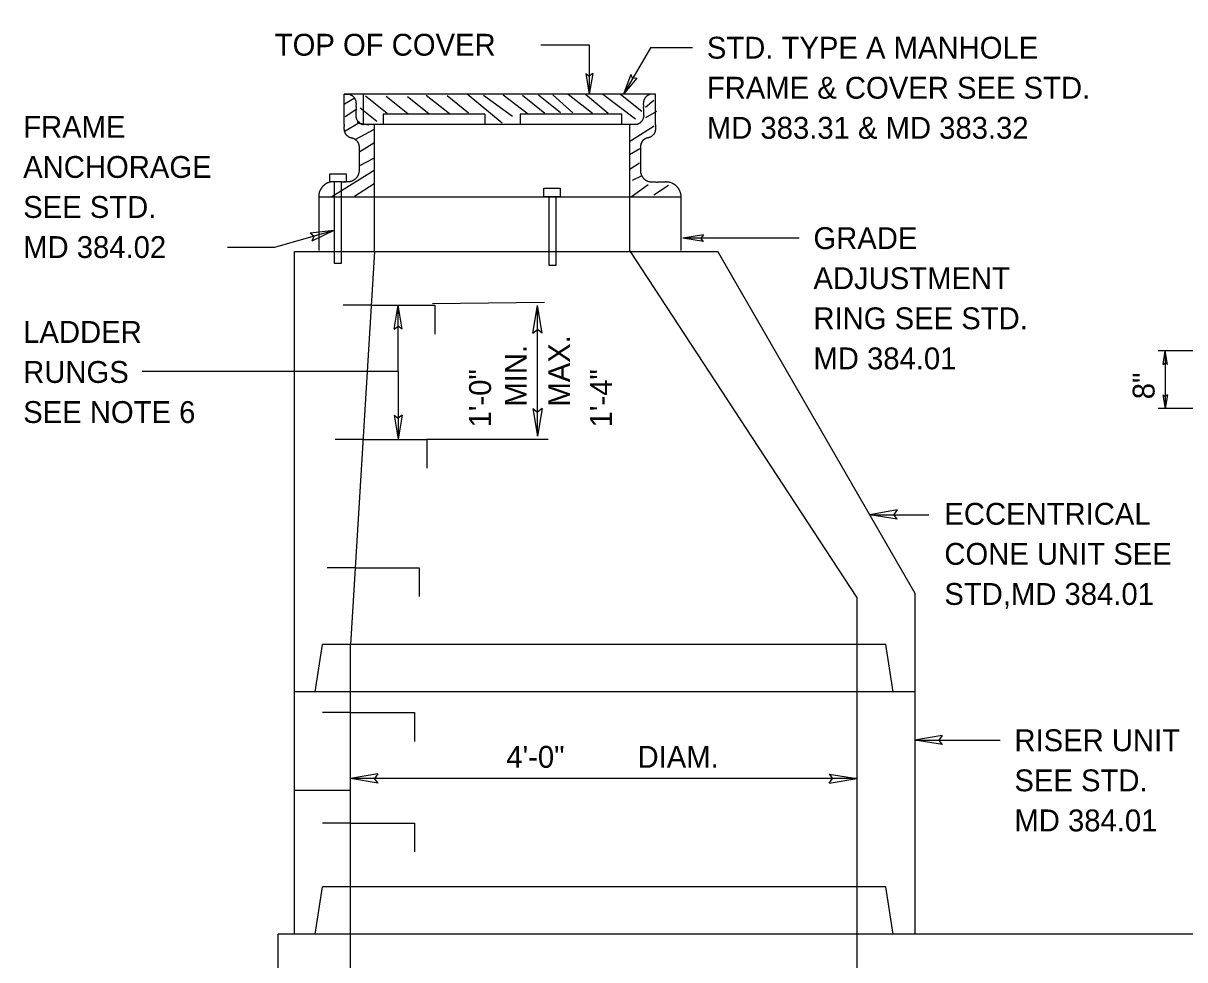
# Model space of a CAD drawing. Extents: x 1.8 to 9.1, y -6 to 4.
# Drawn here: x 1.845 to 5.032, y -0.238 to 2.333 of the extents above; entities that cross this region are included whole.
import ezdxf

# ---------------------------------------------------------------- set-up
doc = ezdxf.new("R2010")
doc.units = 0
for name, color, linetype in [('DETL-DIMS', 7, 'Continuous'), ('DETL-LINE', 7, 'Continuous'), ('DETL-NOTE', 7, 'Continuous'), ('DETL-PATT', 7, 'Continuous')]:
    doc.layers.add(name, color=color, linetype=linetype)

msp = doc.modelspace()

# ---------------------------------------------------------------- linework, layer by layer
at = {"layer": 'DETL-DIMS'}
for p, q in [((3.2647, 2.2738), (3.3979, 2.2738)), ((3.3979, 2.2738), (3.3979, 2.1382)), ((3.5656, 2.2657), (3.492, 2.1382)), ((3.6811, 2.2657), (3.5656, 2.2657)), ((3.3885, 2.1948), (3.3979, 2.1382)), ((3.3885, 2.1948), (3.3979, 2.1877)), ((3.4073, 2.1948), (3.3979, 2.1382)), ((3.4073, 2.1948), (3.3979, 2.1877)), ((3.5122, 2.1919), (3.492, 2.1382)), ((3.5285, 2.1825), (3.492, 2.1382)), ((3.5122, 2.1919), (3.5168, 2.1811)), ((3.5285, 2.1825), (3.5168, 2.1811)), ((2.5351, 1.7185), (2.6983, 1.7645)), ((2.6317, 1.7572), (2.6983, 1.7645)), ((2.6317, 1.7572), (2.6427, 1.7488)), ((2.6377, 1.736), (2.6983, 1.7645)), ((2.6377, 1.736), (2.6427, 1.7488)), ((3.711, 1.7524), (3.6544, 1.743)), ((3.9735, 1.743), (3.6544, 1.743)), ((3.711, 1.7335), (3.6544, 1.743)), ((3.711, 1.7524), (3.704, 1.743)), ((3.711, 1.7335), (3.704, 1.743)), ((2.4048, 1.7185), (2.5351, 1.7185)), ((2.9675, 1.5639), (3.2747, 1.567)), ((2.8623, 1.4931), (2.8733, 1.5592)), ((2.8733, 1.3766), (2.8733, 1.5592)), ((2.8843, 1.4931), (2.8733, 1.5592)), ((3.2431, 1.4826), (3.2557, 1.5581)), ((3.2557, 1.1996), (3.2557, 1.5581)), ((3.2683, 1.4826), (3.2557, 1.5581)), ((2.8623, 1.4931), (2.8733, 1.5014)), ((2.8843, 1.4931), (2.8733, 1.5014)), ((3.2431, 1.4826), (3.2557, 1.4921)), ((3.2683, 1.4826), (3.2557, 1.4921)), ((5.0766, 1.4338), (4.9586, 1.4338)), ((4.9721, 1.3961), (4.9783, 1.4338)), ((4.9847, 1.3961), (4.9783, 1.4338)), ((4.9783, 1.4338), (4.9783, 1.275)), ((2.8733, 1.3766), (2.1711, 1.3766)), ((2.8733, 1.3766), (2.8733, 1.1913)), ((4.9721, 1.3961), (4.9784, 1.4008)), ((4.9847, 1.3961), (4.9784, 1.4008)), ((4.9719, 1.3128), (4.9783, 1.275)), ((4.9719, 1.3128), (4.9782, 1.3081)), ((4.9845, 1.3128), (4.9782, 1.3081)), ((4.9845, 1.3128), (4.9783, 1.275)), ((3.2431, 1.275), (3.2557, 1.1996)), ((3.2431, 1.275), (3.2557, 1.2656)), ((3.2683, 1.275), (3.2557, 1.1996)), ((3.2683, 1.275), (3.2557, 1.2656)), ((5.1362, 1.275), (4.9586, 1.275)), ((2.8623, 1.2573), (2.8733, 1.1913)), ((2.8623, 1.2573), (2.8733, 1.2491)), ((2.8843, 1.2573), (2.8733, 1.1913)), ((2.8843, 1.2573), (2.8733, 1.2491)), ((3.2852, 1.1906), (2.9514, 1.1904)), ((4.2425, 0.9973), (4.1673, 0.9832)), ((4.2425, 0.9973), (4.2333, 0.9845)), ((4.243, 0.9721), (4.1673, 0.9832)), ((4.1673, 0.9832), (4.3297, 0.9832)), ((4.243, 0.9721), (4.2333, 0.9845)), ((4.3663, 0.3782), (4.2909, 0.3648)), ((4.3665, 0.353), (4.2909, 0.3648)), ((4.2909, 0.3648), (4.5249, 0.3648)), ((4.3663, 0.3782), (4.357, 0.3655)), ((4.3665, 0.353), (4.357, 0.3655)), ((2.8181, 0.2725), (2.7427, 0.2598)), ((2.8182, 0.2474), (2.7427, 0.2598)), ((4.1315, 0.2598), (2.7427, 0.2598)), ((2.8181, 0.2725), (2.8087, 0.2599)), ((2.8182, 0.2474), (2.8087, 0.2599)), ((4.0559, 0.2722), (4.1315, 0.2598)), ((4.0559, 0.2722), (4.0654, 0.2597)), ((4.056, 0.2471), (4.1315, 0.2598)), ((4.056, 0.2471), (4.0654, 0.2597))]:
    msp.add_line(p, q, dxfattribs=at)
at = {"layer": 'DETL-LINE'}
for p, q in [((3.5794, 2.1382), (2.7249, 2.1382)), ((2.7249, 2.0553), (2.7249, 2.1382)), ((2.778, 2.0545), (2.778, 2.1382)), ((3.5794, 2.0553), (3.5794, 2.1382)), ((2.8324, 2.0837), (2.8324, 2.0545)), ((3.1115, 2.0837), (2.8324, 2.0837)), ((3.1115, 2.0837), (3.1115, 2.0545)), ((3.208, 2.0837), (3.208, 2.0545)), ((3.4874, 2.0837), (3.208, 2.0837)), ((3.4874, 2.0545), (3.4874, 2.0837)), ((3.5262, 2.0545), (2.778, 2.0545)), ((2.8081, 1.7066), (2.8081, 2.0545)), ((3.5093, 1.7095), (3.5093, 2.0545)), ((2.7661, 1.9934), (2.7661, 1.9263)), ((3.5382, 1.9934), (3.5382, 1.9263)), ((2.686, 1.8978), (2.686, 1.9196)), ((2.686, 1.9196), (2.7308, 1.9196)), ((2.7308, 1.9196), (2.7308, 1.8978)), ((2.6983, 1.8978), (2.686, 1.8978)), ((2.7184, 1.8978), (2.7308, 1.8978)), ((2.6554, 1.8564), (3.6489, 1.8564)), ((2.6554, 1.8564), (2.6554, 1.7095)), ((3.2731, 1.8564), (3.2731, 1.88)), ((3.2731, 1.88), (3.318, 1.88)), ((3.318, 1.8564), (3.2731, 1.8564)), ((3.2869, 1.8564), (3.2869, 1.6688)), ((3.3071, 1.6688), (3.3071, 1.8564)), ((3.318, 1.88), (3.318, 1.8564)), ((3.6489, 1.8564), (3.6489, 1.7095)), ((2.5894, -0.167), (2.5894, 1.7066)), ((2.5894, 1.7066), (3.7498, 1.7066)), ((2.8081, 1.7066), (2.7427, 0.6274)), ((4.1315, 0.758), (3.5093, 1.7095)), ((3.7498, 1.7076), (4.2909, 0.7687)), ((3.2869, 1.6688), (3.3071, 1.6688)), ((2.7992, 1.5591), (2.7225, 1.5591)), ((2.7768, 1.1908), (2.7002, 1.1908)), ((2.7554, 0.8382), (2.6788, 0.8382)), ((4.2909, 0.7687), (4.2909, -0.167)), ((4.1315, 0.758), (4.1315, -0.412)), ((2.6461, 0.4982), (2.666, 0.6274)), ((4.2112, 0.6274), (2.666, 0.6274)), ((2.7427, -3.2344), (2.7427, 0.6274)), ((4.2312, 0.4982), (4.2112, 0.6274)), ((2.6461, 0.4982), (2.5894, 0.4982)), ((4.2312, 0.4982), (2.6461, 0.4982)), ((4.2909, 0.4982), (4.2312, 0.4982)), ((2.7427, 0.4409), (2.666, 0.4409)), ((2.5894, 0.2282), (2.7427, 0.2282)), ((2.7427, 0.1375), (2.666, 0.1375)), ((2.6461, -0.167), (2.666, -0.0377)), ((4.2112, -0.0377), (2.666, -0.0377)), ((4.2312, -0.167), (4.2112, -0.0377)), ((2.5439, -3.4727), (2.5439, -0.167)), ((2.6461, -0.167), (2.5439, -0.167)), ((4.2312, -0.167), (2.6461, -0.167)), ((5.0988, -0.167), (4.2312, -0.167))]:
    msp.add_line(p, q, dxfattribs=at)
msp.add_lwpolyline([(2.6983, 1.8978), (2.6983, 1.674), (2.7184, 1.674), (2.7184, 1.8978)], close=True, dxfattribs=at)
for points in [[(2.7992, 1.5591), (2.9744, 1.5591), (2.9744, 1.4799)], [(2.7768, 1.1908), (2.952, 1.1908), (2.952, 1.1115)], [(2.7554, 0.8382), (2.9307, 0.8382), (2.9307, 0.759)], [(2.7427, 0.4409), (2.9179, 0.4409), (2.9179, 0.3617)], [(2.7427, 0.1375), (2.9179, 0.1375), (2.9179, 0.0582)]]:
    msp.add_lwpolyline(points, dxfattribs=at)
msp.add_circle((5.69, 3.1109), 0.829, dxfattribs=at)
msp.add_arc((3.5635, 1.9935), 0.0253, 100.5321, 180.1949, dxfattribs=at)
for points in [[(2.7249, 2.1382), (2.7353, 2.138), (2.7405, 2.1373), (2.7437, 2.1361), (2.7452, 2.1353), (2.747, 2.1342), (2.7488, 2.1329), (2.75, 2.1317), (2.7508, 2.131), (2.7512, 2.1306), (2.7517, 2.13), (2.7524, 2.1292), (2.7529, 2.1285), (2.7536, 2.1277), (2.7543, 2.1266), (2.755, 2.1251), (2.7554, 2.1244), (2.7561, 2.1227), (2.7568, 2.1206), (2.7572, 2.1189), (2.7575, 2.1169), (2.7575, 2.115), (2.758, 2.1131), (2.7581, 2.1098), (2.7577, 2.1075), (2.7579, 2.1023), (2.7584, 2.1009), (2.758, 2.099), (2.7581, 2.0948), (2.7576, 2.0934), (2.7578, 2.0887), (2.7573, 2.0872), (2.7575, 2.0816), (2.7571, 2.0797), (2.7572, 2.0769), (2.7577, 2.075), (2.7579, 2.0737), (2.7588, 2.0705), (2.7602, 2.068), (2.761, 2.0664), (2.762, 2.0652), (2.7631, 2.0636), (2.7642, 2.0625), (2.765, 2.0617), (2.7657, 2.0611), (2.7663, 2.0604), (2.7672, 2.0596), (2.769, 2.0584), (2.7708, 2.0573), (2.7716, 2.0569), (2.7723, 2.0565), (2.7734, 2.056), (2.7752, 2.0553), (2.778, 2.0545)], [(3.5794, 2.1382), (3.5689, 2.138), (3.5638, 2.1373), (3.5606, 2.1361), (3.5591, 2.1353), (3.5573, 2.1342), (3.5555, 2.1329), (3.5543, 2.1317), (3.5534, 2.131), (3.553, 2.1306), (3.5526, 2.13), (3.5519, 2.1292), (3.5514, 2.1285), (3.5507, 2.1277), (3.55, 2.1266), (3.5493, 2.1251), (3.5488, 2.1244), (3.5482, 2.1227), (3.5475, 2.1206), (3.5471, 2.1189), (3.5468, 2.1169), (3.5467, 2.115), (3.5463, 2.1131), (3.5461, 2.1098), (3.5466, 2.1075), (3.5464, 2.1023), (3.5459, 2.1009), (3.5463, 2.099), (3.5462, 2.0948), (3.5466, 2.0934), (3.5465, 2.0887), (3.5469, 2.0872), (3.5467, 2.0816), (3.5472, 2.0797), (3.5471, 2.0769), (3.5466, 2.075), (3.5464, 2.0737), (3.5454, 2.0705), (3.544, 2.068), (3.5433, 2.0664), (3.5423, 2.0652), (3.5412, 2.0636), (3.5401, 2.0625), (3.5393, 2.0617), (3.5386, 2.0611), (3.5379, 2.0604), (3.5371, 2.0596), (3.5353, 2.0584), (3.5335, 2.0573), (3.5327, 2.0569), (3.532, 2.0565), (3.5309, 2.056), (3.5291, 2.0553), (3.5262, 2.0545)], [(2.7249, 2.0553), (2.7249, 2.0533), (2.7248, 2.0517), (2.7249, 2.0506), (2.7247, 2.0491), (2.7246, 2.0473), (2.7247, 2.046), (2.7247, 2.0433), (2.7248, 2.0423), (2.7249, 2.0407), (2.7251, 2.0392), (2.7254, 2.0373), (2.7258, 2.0357), (2.7262, 2.0346), (2.7265, 2.0339), (2.7269, 2.033), (2.7276, 2.0315), (2.7286, 2.0297), (2.7297, 2.0281), (2.7307, 2.0268), (2.7319, 2.0257), (2.7326, 2.0248), (2.7333, 2.0243), (2.7354, 2.0225), (2.7371, 2.0215), (2.7387, 2.0206), (2.7395, 2.0202), (2.741, 2.0196), (2.742, 2.0192), (2.7433, 2.0188), (2.7451, 2.0185), (2.747, 2.018), (2.7495, 2.0172), (2.7506, 2.0168), (2.7514, 2.0165), (2.7523, 2.016), (2.753, 2.0156), (2.7538, 2.0153), (2.7548, 2.0145), (2.7558, 2.0138), (2.7567, 2.0132), (2.7579, 2.0122), (2.7588, 2.0113), (2.7594, 2.0107), (2.7609, 2.0089), (2.7621, 2.0071), (2.7628, 2.0058), (2.7635, 2.0048), (2.764, 2.0033), (2.7646, 2.0021), (2.765, 2.0011), (2.7653, 2), (2.7655, 1.999), (2.7658, 1.9974), (2.766, 1.9959), (2.7661, 1.9943), (2.7661, 1.9934)], [(3.5794, 2.0553), (3.5794, 2.0533), (3.5795, 2.0517), (3.5794, 2.0506), (3.5795, 2.0491), (3.5796, 2.0473), (3.5796, 2.046), (3.5796, 2.0433), (3.5794, 2.0423), (3.5794, 2.0407), (3.5792, 2.0392), (3.5788, 2.0373), (3.5784, 2.0357), (3.578, 2.0346), (3.5778, 2.0339), (3.5773, 2.033), (3.5767, 2.0315), (3.5756, 2.0297), (3.5745, 2.0281), (3.5736, 2.0268), (3.5724, 2.0257), (3.5716, 2.0248), (3.571, 2.0243), (3.5689, 2.0225), (3.5672, 2.0215), (3.5656, 2.0206), (3.5647, 2.0202), (3.5633, 2.0196), (3.5623, 2.0192), (3.5609, 2.0188), (3.5592, 2.0185), (3.5573, 2.018), (3.5547, 2.0172), (3.5537, 2.0168), (3.5529, 2.0165), (3.552, 2.016), (3.5513, 2.0156), (3.5505, 2.0153), (3.5494, 2.0145), (3.5484, 2.0138), (3.5476, 2.0132), (3.5464, 2.0122), (3.5455, 2.0113), (3.5449, 2.0107), (3.5434, 2.0089), (3.5421, 2.0071), (3.5414, 2.0058), (3.5408, 2.0048), (3.5402, 2.0033), (3.5396, 2.0021), (3.5393, 2.0011), (3.539, 2), (3.5388, 1.999), (3.5384, 1.9974), (3.5383, 1.9959), (3.5382, 1.9943), (3.5382, 1.9934)], [(2.7661, 1.9263), (2.7656, 1.9222), (2.765, 1.9201), (2.7644, 1.9182), (2.7637, 1.9163), (2.7628, 1.9146), (2.7622, 1.9134), (2.7615, 1.9122), (2.7607, 1.911), (2.7598, 1.9097), (2.7589, 1.9086), (2.7579, 1.9074), (2.7568, 1.9062), (2.756, 1.9055), (2.7552, 1.9048), (2.7543, 1.9042), (2.7532, 1.9033), (2.7524, 1.9027), (2.7514, 1.9021), (2.7506, 1.9016), (2.7492, 1.9008), (2.7477, 1.9002), (2.7459, 1.8993), (2.7429, 1.8984), (2.7407, 1.898), (2.7392, 1.8976), (2.7307, 1.8973), (2.729, 1.8971), (2.7274, 1.8972), (2.7217, 1.8971), (2.7203, 1.897), (2.7184, 1.897), (2.7165, 1.8974), (2.7109, 1.8972), (2.7095, 1.8977), (2.7048, 1.8977), (2.7035, 1.8977), (2.7009, 1.8977), (2.6979, 1.8977), (2.6967, 1.8978), (2.6956, 1.8978), (2.6933, 1.8977), (2.6918, 1.8978), (2.6893, 1.8974), (2.686, 1.8967), (2.6828, 1.8957), (2.6796, 1.8944), (2.678, 1.8937), (2.6768, 1.893), (2.676, 1.8926), (2.6749, 1.8919), (2.6736, 1.891), (2.6726, 1.8904), (2.6713, 1.8894), (2.6701, 1.8885), (2.6687, 1.8873), (2.6679, 1.8863), (2.6664, 1.8847), (2.6655, 1.8838), (2.6651, 1.8834), (2.6646, 1.8828), (2.6641, 1.8822), (2.6636, 1.8815), (2.6631, 1.8808), (2.6625, 1.8798), (2.6621, 1.8789), (2.6613, 1.8779), (2.6607, 1.8769), (2.6599, 1.8755), (2.6593, 1.8741), (2.6578, 1.8708), (2.6566, 1.8666), (2.6556, 1.8623), (2.6554, 1.8564)], [(3.5382, 1.9263), (3.5386, 1.9222), (3.5393, 1.9201), (3.5398, 1.9182), (3.5406, 1.9163), (3.5414, 1.9146), (3.542, 1.9134), (3.5428, 1.9122), (3.5435, 1.911), (3.5445, 1.9097), (3.5454, 1.9086), (3.5464, 1.9074), (3.5475, 1.9062), (3.5483, 1.9055), (3.5491, 1.9048), (3.55, 1.9042), (3.551, 1.9033), (3.5519, 1.9027), (3.5529, 1.9021), (3.5537, 1.9016), (3.5552, 1.9008), (3.5566, 1.9002), (3.5585, 1.8993), (3.5614, 1.8984), (3.5635, 1.898), (3.5651, 1.8976), (3.5736, 1.8973), (3.5752, 1.8971), (3.5769, 1.8972), (3.5825, 1.8971), (3.5839, 1.897), (3.5858, 1.897), (3.5877, 1.8974), (3.5934, 1.8972), (3.5948, 1.8977), (3.5995, 1.8976), (3.6009, 1.8975), (3.6028, 1.898), (3.6066, 1.8978), (3.6075, 1.8983), (3.6088, 1.898), (3.611, 1.8979), (3.6125, 1.8978), (3.6149, 1.8974), (3.6183, 1.8967), (3.6214, 1.8957), (3.6247, 1.8944), (3.6262, 1.8937), (3.6275, 1.893), (3.6283, 1.8926), (3.6294, 1.8919), (3.6307, 1.891), (3.6317, 1.8904), (3.633, 1.8894), (3.6341, 1.8885), (3.6355, 1.8873), (3.6364, 1.8863), (3.6379, 1.8847), (3.6388, 1.8838), (3.6391, 1.8834), (3.6396, 1.8828), (3.6401, 1.8822), (3.6407, 1.8815), (3.6412, 1.8808), (3.6417, 1.8798), (3.6422, 1.8789), (3.643, 1.8779), (3.6436, 1.8769), (3.6443, 1.8755), (3.645, 1.8741), (3.6464, 1.8708), (3.6477, 1.8666), (3.6487, 1.8623), (3.6489, 1.8564)]]:
    msp.add_spline(points, degree=3, dxfattribs=at)
at = {"layer": 'DETL-PATT'}
for p, q in [((3.1587, 2.0589), (3.063, 2.1378)), ((3.2314, 2.0828), (3.1614, 2.1356)), ((3.319, 2.0865), (3.2588, 2.1352)), ((3.353, 2.087), (3.2979, 2.1365)), ((3.4065, 2.085), (3.3403, 2.1372)), ((3.4494, 2.0852), (3.3878, 2.1373)), ((3.5248, 2.07), (3.4348, 2.1369)), ((3.5418, 2.0902), (3.4838, 2.1375)), ((2.7523, 2.1259), (2.7264, 2.1104)), ((2.8436, 2.085), (2.7837, 2.1328)), ((2.8996, 2.0845), (2.8407, 2.1322)), ((2.9574, 2.0838), (2.8995, 2.131)), ((3.0144, 2.0846), (2.9504, 2.1348)), ((3.0662, 2.0859), (3.0083, 2.1337)), ((3.187, 2.077), (3.1077, 2.1342)), ((3.2762, 2.0848), (3.215, 2.1346)), ((3.5516, 2.1022), (3.5752, 2.1213)), ((2.7284, 2.0771), (2.7574, 2.0959)), ((2.8151, 2.0633), (2.7696, 2.0994)), ((3.5818, 2.0905), (3.5522, 2.073)), ((2.7655, 2.059), (2.7279, 2.0362)), ((2.7556, 2.0139), (2.8066, 2.0415)), ((3.5109, 2.0101), (3.576, 2.0516)), ((2.807, 2.0034), (2.7684, 1.9798)), ((3.5366, 1.9882), (3.5083, 1.9716)), ((2.7679, 1.9428), (2.8066, 1.9623)), ((3.5097, 1.9335), (3.536, 1.9501)), ((2.8074, 1.9286), (2.6913, 1.8568)), ((3.5416, 1.9138), (3.5153, 1.9009)), ((2.7539, 1.8584), (2.8079, 1.8928)), ((3.5127, 1.8562), (3.5598, 1.8902)), ((3.5745, 1.862), (3.6148, 1.8882))]:
    msp.add_line(p, q, dxfattribs=at)
msp.add_spline([(2.7681, 2.0608), (2.7618, 2.0612), (2.7618, 2.0596), (2.7634, 2.0596), (2.7683, 2.0579), (2.7732, 2.0579), (2.7781, 2.0563), (2.783, 2.0563), (2.7895, 2.0547), (2.7912, 2.0547), (2.7928, 2.053)], degree=3, dxfattribs=at)

# ---------------------------------------------------------------- texts
at = {"layer": 'DETL-NOTE'}
for s, p in [('TOP OF COVER', (2.5349, 2.2438)), ('STD. TYPE A MANHOLE', (3.7204, 2.2357)), ('FRAME & COVER SEE STD.', (3.7204, 2.1258)), ('FRAME', (1.8446, 2.0184)), ('MD 383.31 & MD 383.32', (3.7204, 2.0158)), ('ANCHORAGE', (1.8446, 1.9084)), ('SEE STD.', (1.8446, 1.7985)), ('GRADE', (4.0128, 1.713)), ('MD 384.02', (1.8446, 1.6885)), ('ADJUSTMENT', (4.0128, 1.603)), ('RING SEE STD.', (4.0128, 1.493)), ('LADDER', (1.8446, 1.4556)), ('MD 384.01', (4.0128, 1.383)), ('RUNGS', (1.8446, 1.3457)), ('SEE NOTE 6', (1.8446, 1.2357)), ('ECCENTRICAL', (4.372, 0.9564)), ('CONE UNIT SEE', (4.372, 0.8464)), ('STD,MD 384.01', (4.372, 0.7364)), ('RISER UNIT', (4.5642, 0.3348)), ('4\'-0"', (3.1702, 0.2893)), ('DIAM.', (3.5302, 0.2893)), ('SEE STD.', (4.5642, 0.2248)), ('MD 384.01', (4.5642, 0.1149))]:
    msp.add_text(s, height=0.05998, dxfattribs=at).set_placement(p)
for s, p in [('MAX.', (3.3451, 1.2806)), ('MIN.', (3.2262, 1.2806)), ('1\'-0"', (3.1281, 1.2236)), ('1\'-4"', (3.4602, 1.2236)), ('8"', (4.9488, 1.3009))]:
    msp.add_text(s, height=0.05998, rotation=90, dxfattribs=at).set_placement(p)

doc.saveas('drawing.dxf')
